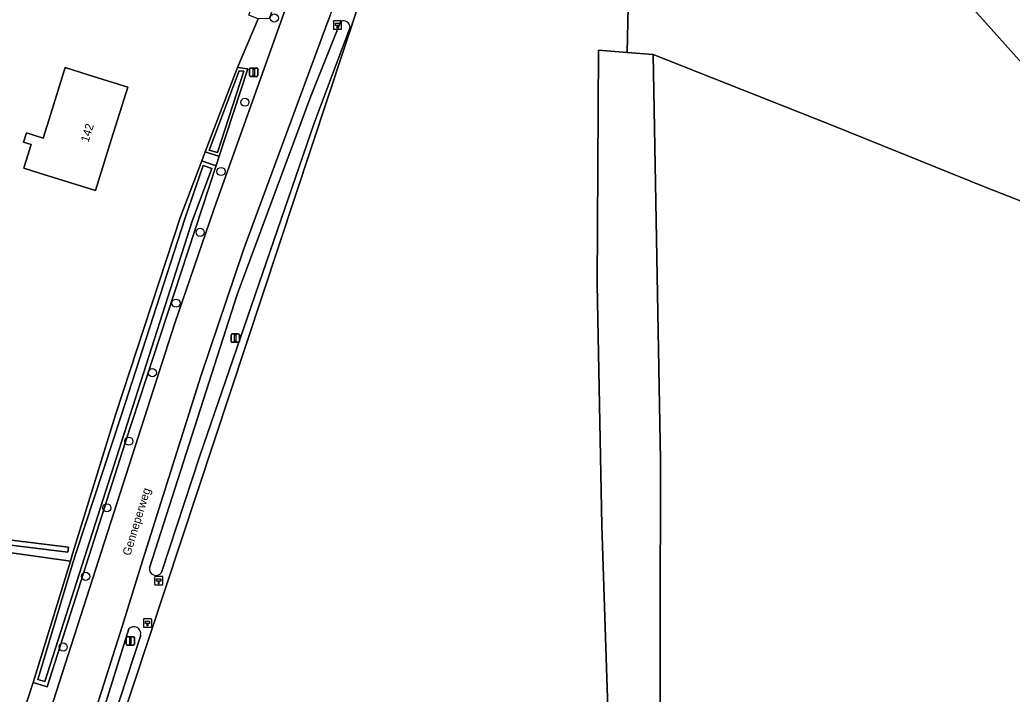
# Model space of a CAD drawing. Extents: x 160203 to 161530, y 379528 to 381797.
# Drawn here: x 160937.5 to 161056.6, y 381119.5 to 381200.5 of the extents above; entities that cross this region are included whole.
import ezdxf

# ---------------------------------------------------------------- set-up
doc = ezdxf.new("R2010")
doc.units = 0
for name, color, linetype in [('IMGEO_Berm_groen', 7, 'Continuous'), ('IMGEO_Boom', 7, 'Continuous'), ('IMGEO_Bouwland', 7, 'Continuous'), ('IMGEO_Erf', 7, 'Continuous'), ('IMGEO_Grasland_agrarisch', 7, 'Continuous'), ('IMGEO_Groenvoorziening', 7, 'Continuous'), ('IMGEO_Haag', 7, 'Continuous'), ('IMGEO_Hectometerpaal', 7, 'Continuous'), ('IMGEO_Hek', 7, 'Continuous'), ('IMGEO_Houtwal', 7, 'Continuous'), ('IMGEO_Lichtmast', 7, 'Continuous'), ('IMGEO_Loofbos', 7, 'Continuous'), ('IMGEO_Oever', 7, 'Continuous'), ('IMGEO_Openbare_ruimte_label', 7, 'Continuous'), ('IMGEO_Pand', 7, 'Continuous'), ('IMGEO_Pand_nummerreeks', 7, 'Continuous'), ('IMGEO_Rijbaan_lokaal_gesloten', 7, 'Continuous'), ('IMGEO_Verkeersbordpaal', 7, 'Continuous'), ('IMGEO_Waterloop', 7, 'Continuous')]:
    doc.layers.add(name, color=color, linetype=linetype)

msp = doc.modelspace()

# ---------------------------------------------------------------- linework, layer by layer
at = {"layer": 'IMGEO_Berm_groen'}
for points in [[(160956.05, 381163.95), (160960.77, 381177.72), (160984.88, 381245.18), (160986.06, 381250), (160986.23, 381250.71), (160990.25, 381267.11), (160991.63, 381275.21), (160992.49, 381282.99), (160992.89, 381292.06), (160989.81, 381291.98), (160988.81, 381291.96), (160988.67, 381289.47), (160988.38, 381284.94), (160987.42, 381279), (160981.87, 381253.14), (160982.87, 381253.03), (160988.4, 381278.82), (160989.38, 381284.84), (160989.67, 381289.41)], [(160991.6, 381288.92), (160990.45, 381275.99), (160988.2, 381264.02), (160985.02, 381251.21), (160982.58, 381251.7), (160981.32, 381245.64), (160982.08, 381245.32), (160982.9, 381245.19), (160982.85, 381244.41), (160971.5, 381211.81), (160967.4, 381200.61), (160966.09, 381200.58), (160963.6, 381194.73), (160964.85, 381194.6), (160961.4, 381184.09), (160961.04, 381182.98), (160950.14, 381149.71), (160940.77, 381120.43), (160939.06, 381120.95), (160937.85, 381117.13), (160940.76, 381116.4), (160956.05, 381163.95)]]:
    msp.add_lwpolyline(points, dxfattribs=at)
at = {"layer": 'IMGEO_Boom'}
for centre in [(160968.03, 381200.68), (160964.5, 381190.58), (160961.64, 381182.26), (160959.14, 381174.97), (160956.23, 381166.46), (160953.38, 381158.13), (160950.56, 381149.9), (160947.92, 381141.91), (160945.39, 381133.68), (160942.69, 381125.2)]:
    msp.add_circle(centre, 0.489, dxfattribs=at)
at = {"layer": 'IMGEO_Bouwland'}
for points in [[(161006.78, 381168.69), (161006.96, 381196.82), (161010.41, 381196.55), (161010.51, 381202), (161007.01, 381202.37), (161006.71, 381247.12), (161000, 381248.89), (160995.77, 381250), (160995.16, 381250.16), (160994.1, 381250.44), (160993.95, 381250), (160939.3, 381085.02), (160943.93, 381083.76), (160975.97, 381079.3), (160994.38, 381077.68), (160995.21, 381078.26), (161000, 381077.09), (161003.55, 381076.23), (161010.95, 381074.65), (161010.97, 381081.3), (161009.28, 381081.26), (161007.34, 381139.77)], [(161073.21, 381098.18), (161078.99, 381136.45), (161083.68, 381168.57), (161053.72, 381180.26), (161034.78, 381187.91), (161013.52, 381196.31), (161014.4, 381147.63), (161014.3, 381086.66), (161013.49, 381081.36), (161013.12, 381077.39), (161013.59, 381077.26), (161068.04, 381060.28), (161068.35, 381062.52)]]:
    msp.add_lwpolyline(points, close=True, dxfattribs=at)
at = {"layer": 'IMGEO_Erf'}
for points in [[(160918.86, 381138.97), (160943.56, 381135.52), (160943.86, 381136.52), (160948.98, 381153.08), (160956.78, 381176.82), (160959.33, 381183.53), (160959.75, 381184.63), (160963.6, 381194.73), (160966.09, 381200.58), (160964.97, 381201.02), (160966.68, 381205.7), (160965.13, 381205.95), (160950.45, 381206.63), (160940.17, 381205.98), (160925.58, 381203.46)], [(160919.77, 381140.08), (160943.31, 381137.19), (160943.24, 381136.59), (160919.06, 381139.56)]]:
    msp.add_lwpolyline(points, dxfattribs=at)
msp.add_lwpolyline([(160939.84, 381182.08), (160937.95, 381182.67), (160938, 381182.82), (160938.84, 381185.5), (160937.91, 381185.79), (160938.26, 381186.9), (160940.27, 381186.27), (160940.98, 381188.54), (160942.93, 381194.74), (160945.68, 381193.87), (160950.45, 381192.38), (160948.5, 381186.17), (160946.55, 381179.97)], close=True, dxfattribs=at)
at = {"layer": 'IMGEO_Grasland_agrarisch'}
msp.add_lwpolyline([(160937.85, 381117.13), (160939.06, 381120.95), (160943.56, 381135.52), (160918.86, 381138.97)], dxfattribs=at)
at = {"layer": 'IMGEO_Groenvoorziening'}
for points in [[(160939.3, 381085.02), (160993.95, 381250), (160994.1, 381250.44), (160995.16, 381250.16), (160995.77, 381250), (161000, 381248.89), (161006.71, 381247.12), (161007.7, 381246.82), (161007.76, 381248.66), (161008.06, 381248.65), (161008.36, 381248.48), (161016.01, 381243.99), (161022.68, 381238.69), (161024.53, 381237.38), (161026.74, 381235.73), (161028.68, 381234.18), (161032.69, 381230.87), (161034.94, 381228.57), (161036.27, 381227.49), (161059.7, 381201.99)], [(160974.68, 381200.87), (160974.47, 381200.28), (160964.36, 381173), (160959.23, 381157.7), (160952.02, 381134.89), (160949.77, 381127.68), (160934.49, 381079.74)], [(160953.05, 381134.71), (160963.59, 381167.51), (160972.42, 381191.32), (160976.03, 381200.31)], [(160977.15, 381199.6), (160972.82, 381188.05), (160959.08, 381148.14)], [(160959.08, 381148.14), (160954.48, 381134.13)], [(160944.58, 381103.93), (160938.74, 381085.3), (160937.56, 381085.73), (160950.58, 381127.38)], [(160951.99, 381126.64), (160944.58, 381103.93)]]:
    msp.add_lwpolyline(points, dxfattribs=at)
for points in [[(161082.58, 381175.75), (161077.67, 381178.3), (161070.58, 381182.79), (161061.58, 381191.03), (161050.68, 381203.28), (161037.87, 381219.57), (161034.13, 381223.39), (161013.62, 381201.68), (161010.51, 381202), (161010.41, 381196.55), (161013.52, 381196.31), (161034.78, 381187.91), (161053.72, 381180.26), (161083.68, 381168.57), (161084.61, 381170.36), (161086.05, 381169.75), (161087.55, 381174.03), (161086.17, 381174.41)], [(160961.4, 381184.09), (160961.08, 381184.2), (160960.08, 381184.52), (160959.75, 381184.63), (160959.33, 381183.53), (160959.66, 381183.43), (160960.71, 381183.08), (160961.04, 381182.98)], [(160919.77, 381140.08), (160931.68, 381176.29), (160931.1, 381176.45), (160928.12, 381167.36), (160918.98, 381139.57), (160919.06, 381139.56), (160943.24, 381136.59), (160943.31, 381137.19)]]:
    msp.add_lwpolyline(points, close=True, dxfattribs=at)
for centre, radius, start, end in [((160976.3, 381199.5), 0.852, 6.5141, 108.5302), ((160953.83, 381134.58), 0.788, 170.441, 324.9041), ((160951.17, 381126.8), 0.831, 348.833, 136.0447)]:
    msp.add_arc(centre, radius, start, end, dxfattribs=at)
at = {"layer": 'IMGEO_Haag'}
msp.add_lwpolyline([(160931.68, 381176.29), (160931.12, 381176.48), (160931.1, 381176.45), (160928.12, 381167.36), (160918.98, 381139.57), (160919.06, 381139.56), (160943.24, 381136.59), (160943.31, 381137.19), (160919.77, 381140.08)], close=True, dxfattribs=at)
at = {"layer": 'IMGEO_Hectometerpaal'}
for p, q in [((160975.12, 381200.25), (160975.12, 381199.41)), ((160975.12, 381200.25), (160975.12, 381199.41)), ((160976.03, 381200.33), (160975.19, 381200.33)), ((160976.03, 381200.33), (160975.19, 381200.33)), ((160975.2, 381199.33), (160976.04, 381199.33)), ((160975.2, 381199.33), (160976.04, 381199.33)), ((160976.11, 381199.42), (160976.11, 381200.26)), ((160976.11, 381199.42), (160976.11, 381200.26)), ((160953.66, 381133.56), (160953.66, 381132.72)), ((160953.66, 381133.56), (160953.66, 381132.72)), ((160954.57, 381133.65), (160953.73, 381133.65)), ((160954.57, 381133.65), (160953.73, 381133.65)), ((160953.74, 381132.65), (160954.58, 381132.65)), ((160953.74, 381132.65), (160954.58, 381132.65)), ((160954.66, 381132.73), (160954.66, 381133.57)), ((160954.66, 381132.73), (160954.66, 381133.57)), ((160952.31, 381128.5), (160952.31, 381127.66)), ((160952.31, 381128.5), (160952.31, 381127.66)), ((160953.22, 381128.58), (160952.38, 381128.58)), ((160953.22, 381128.58), (160952.38, 381128.58)), ((160953.31, 381127.67), (160953.31, 381128.51)), ((160953.31, 381127.67), (160953.31, 381128.51)), ((160952.39, 381127.58), (160953.23, 381127.58)), ((160952.39, 381127.58), (160953.23, 381127.58))]:
    msp.add_line(p, q, dxfattribs=at)
for points in [[(160975.64, 381199.48), (160975.58, 381199.48), (160975.58, 381199.78), (160975.36, 381199.78), (160975.36, 381200.05), (160975.86, 381200.05), (160975.86, 381199.78), (160975.64, 381199.78), (160975.64, 381199.48)], [(160954.18, 381132.79), (160954.12, 381132.79), (160954.12, 381133.1), (160953.9, 381133.1), (160953.9, 381133.37), (160954.4, 381133.37), (160954.4, 381133.1), (160954.18, 381133.1), (160954.18, 381132.79)], [(160952.83, 381127.73), (160952.77, 381127.73), (160952.77, 381128.03), (160952.55, 381128.03), (160952.55, 381128.3), (160953.05, 381128.3), (160953.05, 381128.03), (160952.83, 381128.03), (160952.83, 381127.73)]]:
    msp.add_lwpolyline(points, dxfattribs=at)
for centre, start, end in [((160975.19, 381200.25), 92.4484, 184.2845), ((160975.19, 381200.25), 92.4484, 184.2845), ((160975.19, 381199.41), 182.4484, 274.2845), ((160975.19, 381199.41), 182.4484, 274.2845), ((160976.04, 381200.25), 2.4484, 94.2845), ((160976.04, 381200.25), 2.4484, 94.2845), ((160976.04, 381199.41), 272.4484, 4.2845), ((160976.04, 381199.41), 272.4484, 4.2845), ((160953.74, 381133.57), 92.4484, 184.2845), ((160953.74, 381133.57), 92.4484, 184.2845), ((160953.74, 381132.73), 182.4484, 274.2845), ((160953.74, 381132.73), 182.4484, 274.2845), ((160954.58, 381133.57), 2.4484, 94.2845), ((160954.58, 381133.57), 2.4484, 94.2845), ((160954.58, 381132.73), 272.4484, 4.2845), ((160954.58, 381132.73), 272.4484, 4.2845), ((160952.39, 381128.5), 92.4484, 184.2845), ((160952.39, 381128.5), 92.4484, 184.2845), ((160953.23, 381128.5), 2.4484, 94.2845), ((160953.23, 381128.5), 2.4484, 94.2845), ((160952.39, 381127.66), 182.4484, 274.2845), ((160952.39, 381127.66), 182.4484, 274.2845), ((160953.23, 381127.66), 272.4484, 4.2845), ((160953.23, 381127.66), 272.4484, 4.2845)]:
    msp.add_arc(centre, 0.0779, start, end, dxfattribs=at)
at = {"layer": 'IMGEO_Hek'}
msp.add_lwpolyline([(160995.16, 381250.16), (160994.1, 381250.44), (160993.95, 381250), (160939.3, 381085.02), (160943.93, 381083.76), (160975.97, 381079.3), (160994.38, 381077.68), (160995.21, 381078.26), (161000, 381077.09), (161003.55, 381076.23), (161010.95, 381074.65)], dxfattribs=at)
at = {"layer": 'IMGEO_Houtwal'}
msp.add_lwpolyline([(161010.97, 381081.3), (161013.49, 381081.36), (161014.3, 381086.66), (161014.4, 381147.63), (161013.52, 381196.31), (161010.41, 381196.55), (161006.96, 381196.82), (161006.78, 381168.69), (161007.34, 381139.77), (161009.28, 381081.26)], close=True, dxfattribs=at)
at = {"layer": 'IMGEO_Lichtmast'}
for p, q in [((160962.85, 381161.87), (160962.85, 381162.67)), ((160962.85, 381162.67), (160962.85, 381161.87)), ((160962.95, 381162.77), (160963.74, 381162.77)), ((160963.74, 381162.77), (160962.95, 381162.77)), ((160963.84, 381162.67), (160963.84, 381161.87)), ((160963.84, 381161.87), (160963.84, 381162.67)), ((160963.74, 381161.77), (160962.95, 381161.77)), ((160962.95, 381161.77), (160963.74, 381161.77)), ((160950.25, 381125.53), (160950.25, 381126.33)), ((160950.25, 381126.33), (160950.25, 381125.53)), ((160950.35, 381126.43), (160951.14, 381126.43)), ((160951.14, 381126.43), (160950.35, 381126.43)), ((160951.14, 381125.43), (160950.35, 381125.43)), ((160950.35, 381125.43), (160951.14, 381125.43)), ((160951.24, 381126.33), (160951.24, 381125.53)), ((160951.24, 381125.53), (160951.24, 381126.33))]:
    msp.add_line(p, q, dxfattribs=at)
for points in [[(160963.27, 381162.65), (160963.42, 381162.65), (160963.42, 381161.9), (160963.27, 381161.9), (160963.27, 381162.65)], [(160950.67, 381126.3), (160950.82, 381126.3), (160950.82, 381125.55), (160950.67, 381125.55), (160950.67, 381126.3)]]:
    msp.add_lwpolyline(points, dxfattribs=at)
for centre, start, end in [((160962.95, 381162.67), 90, 180), ((160962.95, 381162.67), 90, 180), ((160963.74, 381162.67), 0, 90), ((160963.74, 381162.67), 360, 90), ((160962.95, 381161.87), 180, 270), ((160962.95, 381161.87), 180, 270), ((160963.74, 381161.87), 270, 0), ((160963.74, 381161.87), 270, 0), ((160950.35, 381126.33), 90, 180), ((160950.35, 381126.33), 90, 180), ((160950.35, 381125.53), 180, 270), ((160950.35, 381125.53), 180, 270), ((160951.14, 381126.33), 0, 90), ((160951.14, 381126.33), 360, 90), ((160951.14, 381125.53), 270, 0), ((160951.14, 381125.53), 270, 0)]:
    msp.add_arc(centre, 0.1, start, end, dxfattribs=at)
at = {"layer": 'IMGEO_Loofbos'}
msp.add_lwpolyline([(161059.7, 381201.99), (161036.27, 381227.49), (161027.79, 381218.64), (161028.01, 381218.43), (161012.39, 381202.11), (161010.47, 381202.34), (161009.11, 381229.12), (161007.23, 381233.18), (161007.7, 381246.74), (161007.7, 381246.82), (161006.71, 381247.12), (161007.01, 381202.37), (161010.51, 381202), (161013.62, 381201.68), (161034.13, 381223.39), (161037.87, 381219.57), (161050.68, 381203.28), (161061.58, 381191.03)], dxfattribs=at)
at = {"layer": 'IMGEO_Oever'}
for points in [[(160964.85, 381194.6), (160963.6, 381194.73), (160959.75, 381184.63), (160960.08, 381184.52), (160961.08, 381184.2), (160961.4, 381184.09)], [(160960.23, 381184.83), (160963.82, 381194.36), (160964.39, 381194.3), (160961.2, 381184.56)], [(160961.04, 381182.98), (160960.71, 381183.08), (160959.66, 381183.43), (160959.33, 381183.53), (160956.78, 381176.82), (160948.98, 381153.08), (160943.86, 381136.52), (160943.56, 381135.52), (160939.06, 381120.95), (160940.77, 381120.43), (160950.14, 381149.71)], [(160939.64, 381121.3), (160943.88, 381135.42), (160944.19, 381136.41), (160949.68, 381153.06), (160957.28, 381176.57), (160959.5, 381182.97), (160960.55, 381182.63), (160958.17, 381176.29), (160949.71, 381149.93), (160940.49, 381121.04)]]:
    msp.add_lwpolyline(points, close=True, dxfattribs=at)
at = {"layer": 'IMGEO_Pand'}
msp.add_lwpolyline([(160950.45, 381192.38), (160945.68, 381193.87), (160942.93, 381194.74), (160940.98, 381188.54), (160940.27, 381186.27), (160938.26, 381186.9), (160937.91, 381185.79), (160938.84, 381185.5), (160938, 381182.82), (160937.95, 381182.67), (160939.84, 381182.08), (160946.55, 381179.97), (160948.5, 381186.17)], close=True, dxfattribs=at)
at = {"layer": 'IMGEO_Rijbaan_lokaal_gesloten'}
msp.add_lwpolyline([(160934.49, 381079.74), (160949.77, 381127.68), (160952.02, 381134.89), (160959.23, 381157.7), (160964.36, 381173), (160974.47, 381200.28), (160974.68, 381200.87), (160988.22, 381238.39), (160991.59, 381248.5), (160986.23, 381250.71), (160986.06, 381250), (160984.88, 381245.18), (160960.77, 381177.72), (160956.05, 381163.95), (160940.76, 381116.4)], dxfattribs=at)
at = {"layer": 'IMGEO_Verkeersbordpaal'}
for p, q in [((160965.07, 381193.78), (160965.07, 381194.58)), ((160965.07, 381194.58), (160965.07, 381193.78)), ((160965.17, 381194.68), (160965.96, 381194.68)), ((160965.96, 381194.68), (160965.17, 381194.68)), ((160966.06, 381194.58), (160966.06, 381193.78)), ((160966.06, 381193.78), (160966.06, 381194.58)), ((160965.96, 381193.68), (160965.17, 381193.68)), ((160965.17, 381193.68), (160965.96, 381193.68))]:
    msp.add_line(p, q, dxfattribs=at)
msp.add_lwpolyline([(160965.49, 381194.55), (160965.64, 381194.55), (160965.64, 381193.8), (160965.49, 381193.8), (160965.49, 381194.55)], dxfattribs=at)
for centre, start, end in [((160965.17, 381194.58), 90, 180), ((160965.17, 381194.58), 90, 180), ((160965.96, 381194.58), 0, 90), ((160965.96, 381194.58), 360, 90), ((160965.17, 381193.78), 180, 270), ((160965.17, 381193.78), 180, 270), ((160965.96, 381193.78), 270, 0), ((160965.96, 381193.78), 270, 0)]:
    msp.add_arc(centre, 0.1, start, end, dxfattribs=at)
at = {"layer": 'IMGEO_Waterloop'}
for points in [[(160976.03, 381200.31), (160972.42, 381191.32), (160963.59, 381167.51), (160953.05, 381134.71)], [(160954.48, 381134.13), (160959.08, 381148.14), (160972.82, 381188.05), (160977.15, 381199.6)], [(160950.58, 381127.38), (160937.56, 381085.73), (160938.74, 381085.3), (160944.58, 381103.93), (160951.99, 381126.64)]]:
    msp.add_lwpolyline(points, dxfattribs=at)
for points in [[(160960.23, 381184.83), (160961.2, 381184.56), (160964.39, 381194.3), (160963.82, 381194.36)], [(160960.55, 381182.63), (160959.5, 381182.97), (160957.28, 381176.57), (160949.68, 381153.06), (160944.19, 381136.41), (160943.88, 381135.42), (160939.64, 381121.3), (160940.49, 381121.04), (160949.71, 381149.93), (160958.17, 381176.29)]]:
    msp.add_lwpolyline(points, close=True, dxfattribs=at)
for centre, radius, start, end in [((160976.3, 381199.5), 0.852, 6.5141, 108.5302), ((160953.83, 381134.58), 0.788, 170.441, 324.9041), ((160951.17, 381126.8), 0.831, 348.833, 136.0447)]:
    msp.add_arc(centre, radius, start, end, dxfattribs=at)

# ---------------------------------------------------------------- texts
at = {"layer": 'IMGEO_Openbare_ruimte_label'}
msp.add_text('Genneperweg', height=1, rotation=72.9605, dxfattribs=at).set_placement((160950.73, 381136.08))
at = {"layer": 'IMGEO_Pand_nummerreeks'}
msp.add_text('142', height=1, rotation=72.5594, dxfattribs=at).set_placement((160945.71, 381185.7))

doc.saveas('drawing.dxf')
